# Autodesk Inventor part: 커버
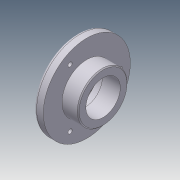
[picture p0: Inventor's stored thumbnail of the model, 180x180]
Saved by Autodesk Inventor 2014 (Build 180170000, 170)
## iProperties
Company: 한국ATC센터
Created: 2014-10
Part Number: 커버
Document SubType Name: Modeling
Designer: 한국ATC센터
Density: 2.71 g/cm^3
Material: 알루미늄-6061
Mass: 189.975 g
Surface Area: 197.126 cm^2
Volume: 70.1013 cm^3
Appearance: 알루미늄 - 평지
Author: KYOUNG IL JANG
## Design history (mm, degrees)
sketch "스케치1"
  geometry: L1 (-13.5, 0)-(13.5, 0); L2 (-13.5, 0)-(-13.5, 45.5); L3 (-13.5, 45.5)-(-3.5, 45.5); L4 (-3.5, 45.5)-(-3.5, 26); L5 (-3.5, 26)-(13.5, 26); L6 (13.5, 26)-(13.5, 0); 2 further points
  constraints: 12 end point, 3 parallel, 2 perpendicular, 1 coincident, 1 horizontal, 1 midpoint
  dimensions: "d0" = 27 distance of L1.start L1.end; "d1" = 91 diameter of L3 L1; "d2" = 52 diameter of L5 L1; "d3" = 10 distance of L2.end L3.end
revolve "회전1" sketch "스케치1" stored, may be unused: angle "d4" = 90 deg
hole "구멍1" diameter "d7" = 36; stored, may be unused: countersink angle "d11" = 90 deg, drill point angle "d13" = 118 deg; dims "d5" = 10, "d6" = 10, "d8" = 6, "d9" = 40, "d10" = 8.3, "d12" = 8
sketch "스케치2"
  geometry: 2 further points
  constraints: 1 vertical alignment
  dimensions: "d14" = 35 distance of point (0, 0) point (0, 35)
hole "구멍2" sketch "스케치2" at (0, 35) diameter "d15" = 4.5; stored, may be unused: countersink angle "d19" = 90 deg, drill point angle "d21" = 118 deg; dims "d16" = 6, "d17" = 8, "d18" = 4.4, "d20" = 8
chamfer "모따기1" distance "d25" = 0.8; stored, may be unused: second distance "d26" = 2, angle "d27" = 30 deg
fillet "모깎기1" dims "d28" = 0.1, "d29" = 3
chamfer "모따기2" distance "d30" = 1; stored, may be unused: second distance "d31" = 2, angle "d32" = 30 deg
node "솔리드1"
pattern_circular "원형 패턴1" dims angle "d23" = 360 deg
